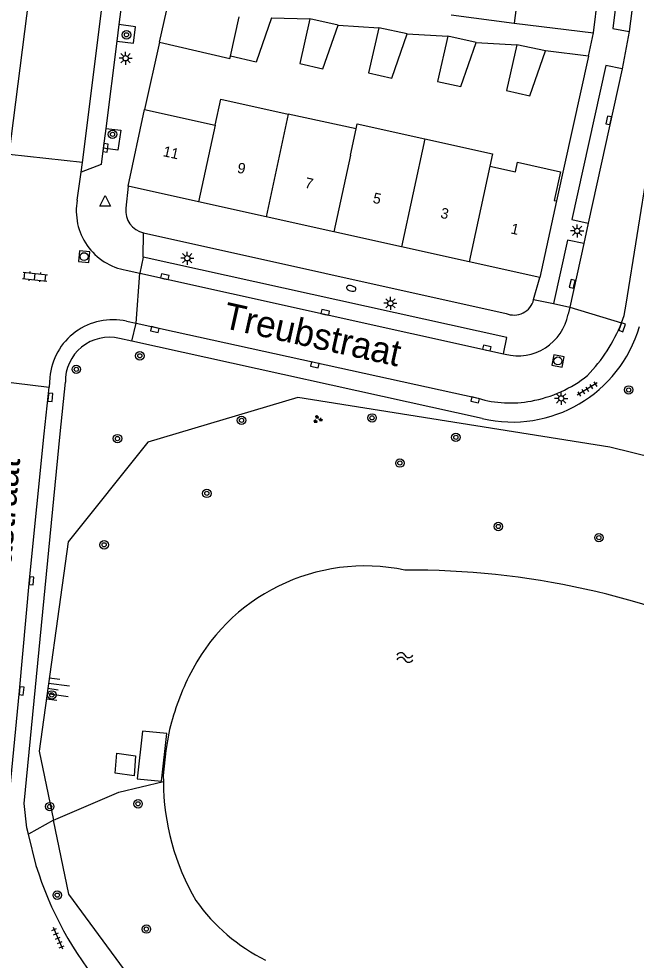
# Model space of a CAD drawing. Extents: x 131000 to 133014, y 396499 to 399001.
# Drawn here: x 131743 to 131801.6, y 397450 to 397539.4 of the extents above; entities that cross this region are included whole.
import ezdxf

# ---------------------------------------------------------------- set-up
doc = ezdxf.new("R2010")
doc.units = 0
for name, color, linetype in [('gg-afsc-erfafscheiding', 7, 'Continuous'), ('gg-afsc-muur', 7, 'Continuous'), ('gg-anno-huisnummerreeks BGT', 7, 'Continuous'), ('gg-anno-openbare ruimte label', 7, 'Continuous'), ('gg-bbg-bijgebouw', 7, 'Continuous'), ('gg-bbg-gedigitaliseerde bebouwing', 7, 'Continuous'), ('gg-bbg-gedigitaliseerde bijgebouw', 7, 'Continuous'), ('gg-bbg-hoofdgebouw', 7, 'Continuous'), ('gg-bbg-tussenscheiding', 7, 'Continuous'), ('gg-knt-BGT kruinlijn', 7, 'Continuous'), ('gg-knt-verharding', 7, 'Continuous'), ('gg-knt-verharding nz', 7, 'Continuous'), ('gg-kntw-beschoeiing', 7, 'Continuous'), ('gg-kwrk-betonelement', 7, 'Continuous'), ('gg-kwrk-uitstroombak niveau min 01', 7, 'Continuous'), ('gt-grn-groengrens', 7, 'Continuous'), ('gt-grn-weggrens', 7, 'Continuous'), ('gt-symb-boom', 7, 'Continuous'), ('gt-symb-brandkraan', 7, 'Continuous'), ('gt-symb-groenvak', 7, 'Continuous'), ('gt-symb-klinker verharding', 7, 'Continuous'), ('gt-symb-kolk', 7, 'Continuous'), ('gt-symb-lichtmast', 7, 'Continuous'), ('gt-symb-rioolschacht', 7, 'Continuous'), ('gt-symb-talud symbool', 7, 'Continuous'), ('gt-symb-tegel verharding', 7, 'Continuous'), ('gt-symb-waterafsluiter', 7, 'Continuous'), ('gt-symb-watersymbool', 7, 'Continuous')]:
    doc.layers.add(name, color=color, linetype=linetype)

# ---------------------------------------------------------------- blocks, each defined once
blk = doc.blocks.new('gt0-KOLK')
at = {"layer": 'gt-symb-kolk'}
blk.add_lwpolyline([(0, 0), (0.375, 0), (0.375, 0.4), (-0.375, 0.4), (-0.375, 0), (0, 0)], dxfattribs=at)
blk = doc.blocks.new('gt0-BOOM')
at = {"layer": 'gt-symb-boom'}
for radius in [0.4, 0.2]:
    blk.add_circle((0, 0), radius, dxfattribs=at)
blk = doc.blocks.new('gt0-LMAST')
at = {"layer": 'gt-symb-lichtmast'}
for p, q in [((-0.182, 0.173), (-0.447, 0.438)), ((-0.005, 0.246), (-0.005, 0.621)), ((0.172, 0.173), (0.437, 0.438)), ((-0.255, -0.004), (-0.63, -0.004)), ((-0.182, -0.181), (-0.447, -0.446)), ((-0.005, -0.254), (-0.005, -0.629)), ((0.437, -0.446), (0.172, -0.181)), ((0.245, -0.004), (0.62, -0.004))]:
    blk.add_line(p, q, dxfattribs=at)
blk.add_circle((-0.005, -0.004), 0.25, dxfattribs=at)
blk = doc.blocks.new('gt0-RS')
at = {"layer": 'gt-symb-rioolschacht'}
blk.add_lwpolyline([(-0.5, -0.5), (0.5, -0.5), (0.5, 0.5), (-0.5, 0.5)], close=True, dxfattribs=at)
blk.add_circle((0, 0), 0.375, dxfattribs=at)
blk = doc.blocks.new('gt0-WAFSL')
at = {"layer": 'gt-symb-waterafsluiter'}
for p, q in [((-0.5, -0.333), (0, 0.667)), ((0, 0.667), (0.5, -0.333)), ((0.5, -0.333), (-0.5, -0.333))]:
    blk.add_line(p, q, dxfattribs=at)
blk = doc.blocks.new('gt0-BR')
at = {"layer": 'gt-symb-brandkraan'}
for centre, radius, start, end in [((-0.244, 0), 0.206, 107.56694, 252.43307), ((0.599, -2.664), 3, 106.89205, 107.56694), ((0, -0.691), 0.938, 73.10799, 106.89205), ((-0.599, -2.664), 3, 72.43309, 73.10799), ((0.244, 0), 0.206, 287.56695, 72.43309), ((0.599, 2.664), 3, 252.43307, 253.10797), ((0, 0.691), 0.938, 253.10797, 286.89206), ((-0.599, 2.664), 3, 286.89206, 287.56695)]:
    blk.add_arc(centre, radius, start, end, dxfattribs=at)
blk = doc.blocks.new('gt0-TEG1')
at = {"layer": 'gt-symb-tegel verharding'}
for p, q in [((-1.125, 0), (1.125, 0)), ((-0.9, -0.25), (-0.9, 0.25)), ((-0.45, -0.25), (-0.45, 0.25)), ((0, -0.25), (0, 0.25)), ((0.45, -0.25), (0.45, 0.25)), ((0.9, -0.25), (0.9, 0.25))]:
    blk.add_line(p, q, dxfattribs=at)
blk = doc.blocks.new('gt0-KL1')
at = {"layer": 'gt-symb-klinker verharding'}
for p, q in [((-1.15, 0.3), (1.15, 0.3)), ((-1, -0.3), (-1, 0.3)), ((-0.5, 0.3), (-0.5, 0.45)), ((0, -0.3), (0, 0.3)), ((0.5, 0.3), (0.5, 0.45)), ((1, -0.3), (1, 0.3)), ((-1.15, -0.3), (1.15, -0.3)), ((-0.5, -0.45), (-0.5, -0.3)), ((0.5, -0.45), (0.5, -0.3))]:
    blk.add_line(p, q, dxfattribs=at)
blk = doc.blocks.new('gt0-TALUD_1')
at = {"layer": 'gt-symb-talud symbool'}
for p, q in [((0, -1), (0, 0)), ((-1, -1), (-1, 0)), ((-0.5, -2), (-0.5, 0)), ((0.5, -2), (0.5, 0)), ((1, -1), (1, 0))]:
    blk.add_line(p, q, dxfattribs=at)
blk = doc.blocks.new('gt0-WA')
at = {"layer": 'gt-symb-watersymbool'}
for centre, start, end in [((-0.323, 0.022), 28.07249, 151.92751), ((0.427, 0.422), 208.07248, 331.92751), ((-0.323, -0.428), 28.07249, 151.92751), ((0.427, -0.028), 208.07248, 331.92751)]:
    blk.add_arc(centre, 0.425, start, end, dxfattribs=at)
blk = doc.blocks.new('gt0-GRVAK')
at = {"layer": 'gt-symb-groenvak'}
for p, q in [((-0.11, 0.189), (-0.228, 0.24)), ((-0.182, 0.153), (0.088, 0.153)), ((-0.091, 0.211), (-0.156, 0.322)), ((-0.047, 0.214), (-0.047, 0.393)), ((-0.004, 0.211), (0.061, 0.322)), ((0.015, 0.189), (0.133, 0.24)), ((0.262, -0.052), (0.197, 0.059)), ((0.305, -0.049), (0.305, 0.13)), ((0.349, -0.052), (0.414, 0.059)), ((-0.245, -0.228), (-0.363, -0.177)), ((-0.318, -0.264), (-0.047, -0.264)), ((-0.226, -0.206), (-0.291, -0.095)), ((-0.183, -0.203), (-0.183, -0.024)), ((-0.139, -0.206), (-0.074, -0.095)), ((-0.12, -0.228), (-0.002, -0.177)), ((0.243, -0.074), (0.125, -0.023)), ((0.17, -0.11), (0.441, -0.11)), ((0.368, -0.074), (0.486, -0.023))]:
    blk.add_line(p, q, dxfattribs=at)

msp = doc.modelspace()

# ---------------------------------------------------------------- linework, layer by layer
at = {"layer": 'gg-afsc-erfafscheiding'}
for p, q in [((131784.068, 397539.788), (131790.053, 397539.004)), ((131767.02, 397539.514), (131770.659, 397539.408)), ((131779.898, 397537.994), (131783.763, 397537.787))]:
    msp.add_line(p, q, dxfattribs=at)
at = {"layer": 'gg-afsc-muur'}
for p, q in [((131773.356, 397538.831), (131777.198, 397538.569)), ((131756.39, 397537.19), (131754.98, 397530.82)), ((131786.453, 397537.184), (131790.295, 397536.958)), ((131797.085, 397535.883), (131793.018, 397536.379)), ((131797.085, 397535.883), (131794.05, 397522.13))]:
    msp.add_line(p, q, dxfattribs=at)
at = {"layer": 'gg-bbg-bijgebouw'}
for p, q in [((131756.39, 397537.19), (131757.29, 397541.13)), ((131773.356, 397538.831), (131770.659, 397539.408)), ((131779.898, 397537.994), (131777.198, 397538.569)), ((131786.453, 397537.184), (131783.763, 397537.787)), ((131793.018, 397536.379), (131790.295, 397536.958))]:
    msp.add_line(p, q, dxfattribs=at)
at = {"layer": 'gg-bbg-gedigitaliseerde bebouwing'}
for p, q in [((131790.814, 397545.191), (131790.053, 397539.004)), ((131790.053, 397539.004), (131797.57, 397538.08)), ((131754.98, 397530.82), (131761.666, 397529.333)), ((131775.043, 397528.969), (131768.613, 397530.364))]:
    msp.add_line(p, q, dxfattribs=at)
for points in [[(131761.666, 397529.333), (131762.212, 397531.788), (131768.613, 397530.364)], [(131775.043, 397528.969), (131775.152, 397529.457), (131781.582, 397528.026)], [(131781.582, 397528.026), (131788.005, 397526.597), (131787.744, 397525.423)], [(131787.744, 397525.423), (131790.163, 397524.885), (131790.369, 397525.811), (131794.453, 397524.902), (131793.847, 397522.175), (131794.05, 397522.13)]]:
    msp.add_lwpolyline(points, dxfattribs=at)
at = {"layer": 'gg-bbg-gedigitaliseerde bijgebouw'}
for points in [[(131767.02, 397539.514), (131765.555, 397535.31), (131763.124, 397535.861)], [(131770.659, 397539.408), (131769.698, 397535.169), (131771.904, 397534.668), (131773.356, 397538.831)], [(131777.198, 397538.569), (131776.228, 397534.289), (131778.432, 397533.789), (131779.898, 397537.994)], [(131756.39, 397537.19), (131763.081, 397535.668), (131763.124, 397535.861)], [(131783.763, 397537.787), (131782.786, 397533.476), (131784.986, 397532.978), (131786.453, 397537.184)], [(131790.295, 397536.958), (131789.306, 397532.599), (131791.524, 397532.096), (131793.018, 397536.379)]]:
    msp.add_lwpolyline(points, dxfattribs=at)
at = {"layer": 'gg-bbg-hoofdgebouw'}
for p, q in [((131797.57, 397538.08), (131798.332, 397544.261)), ((131753.41, 397523.53), (131754.98, 397530.82)), ((131760.096, 397522.043), (131753.41, 397523.53)), ((131766.509, 397520.616), (131760.096, 397522.043)), ((131794.05, 397522.13), (131792.47, 397514.84)), ((131772.932, 397519.187), (131766.509, 397520.616)), ((131779.34, 397517.761), (131772.932, 397519.187)), ((131785.762, 397516.332), (131779.34, 397517.761)), ((131792.47, 397514.84), (131785.762, 397516.332))]:
    msp.add_line(p, q, dxfattribs=at)
at = {"layer": 'gg-bbg-tussenscheiding'}
for p, q in [((131763.124, 397535.861), (131763.961, 397539.612)), ((131768.613, 397530.364), (131766.509, 397520.616)), ((131761.666, 397529.333), (131760.096, 397522.043)), ((131774.503, 397526.478), (131775.043, 397528.969)), ((131781.582, 397528.026), (131779.34, 397517.761)), ((131774.503, 397526.478), (131772.932, 397519.187)), ((131787.744, 397525.423), (131785.762, 397516.332))]:
    msp.add_line(p, q, dxfattribs=at)
at = {"layer": 'gg-knt-BGT kruinlijn'}
for points in [[(131861.13, 397483.46), (131799.11, 397498.73), (131769.52, 397503.47), (131755.28, 397499.23), (131747.72, 397489.76), (131744.99, 397469.87), (131746.339, 397463.325)], [(131762.43, 397442.7), (131753.86, 397448.04), (131747.79, 397456.29), (131746.339, 397463.325)]]:
    msp.add_lwpolyline(points, dxfattribs=at)
at = {"layer": 'gg-knt-verharding'}
for p, q in [((131742.143, 397526.534), (131744.895, 397548.371)), ((131752.549, 397538.875), (131752.35, 397537.307)), ((131800.971, 397538.206), (131800.292, 397534.668)), ((131752.35, 397537.307), (131751.301, 397529.017)), ((131751.301, 397529.017), (131751.062, 397527.129)), ((131749.079, 397525.772), (131742.143, 397526.534)), ((131748.955, 397524.858), (131749.079, 397525.772)), ((131748.595, 397522.212), (131748.955, 397524.858)), ((131753.41, 397523.53), (131753.19, 397521.44)), ((131797.072, 397520.014), (131796.653, 397518.073)), ((131754.879, 397519.1), (131789.28, 397511.44)), ((131754.842, 397516.784), (131754.519, 397515.26)), ((131753.238, 397515.547), (131754.519, 397515.26)), ((131754.175, 397510.508), (131754.519, 397515.26)), ((131791.895, 397512.753), (131792.47, 397514.84)), ((131793.768, 397512.396), (131795.313, 397512.032)), ((131795.313, 397512.032), (131795.165, 397511.366)), ((131753.263, 397510.709), (131754.175, 397510.508)), ((131754.175, 397510.508), (131786.634, 397503.382)), ((131753.772, 397508.797), (131752.584, 397509.059)), ((131787.016, 397501.456), (131753.772, 397508.797)), ((131789.03, 397507.605), (131789.206, 397507.566)), ((131739.953, 397505.185), (131745.915, 397504.45)), ((131745.994, 397505.364), (131745.915, 397504.45)), ((131745.464, 397500), (131745.915, 397504.45)), ((131746.983, 397500), (131747.468, 397504.915)), ((131744.675, 397459.029), (131743.963, 397461.997))]:
    msp.add_line(p, q, dxfattribs=at)
for points in [[(131803.137, 397555.819), (131801.569, 397556.036), (131799.411, 397538.498), (131800.971, 397538.206)], [(131753.781, 397548.468), (131753.32, 397544.967), (131752.549, 397538.875)], [(131752.35, 397537.307), (131753.935, 397537.106), (131754.131, 397538.675), (131752.549, 397538.875)], [(131800.292, 397534.668), (131798.737, 397534.977), (131795.513, 397520.351), (131797.072, 397520.014)], [(131751.301, 397529.017), (131752.717, 397528.838), (131752.455, 397526.953), (131751.062, 397527.129)], [(131751.062, 397527.129), (131750.867, 397525.586), (131748.955, 397524.858)], [(131800.232, 397510.549), (131800.478, 397511.242), (131800.672, 397512.334), (131802.768, 397525.352)], [(131796.653, 397518.073), (131795.103, 397518.403), (131793.768, 397512.396)], [(131789.03, 397507.605), (131789.345, 397509.155), (131754.842, 397516.784)], [(131740.962, 397452.964), (131741.081, 397454.971), (131743.11, 397475.613), (131744.057, 397486.134), (131745.464, 397500)], [(131743.963, 397461.997), (131743.817, 397462.604), (131743.566, 397464.92), (131746.983, 397500)]]:
    msp.add_lwpolyline(points, dxfattribs=at)
for centre, radius, start, end in [((131754.195, 397521.163), 5.697, 169.3939, 260.3301), ((131755.352, 397521.221), 2.173, 174.20995, 257.43317), ((131790.026, 397513.214), 1.925, 247.18109, 346.14167), ((131790.4, 397512.266), 4.849, 255.74356, 349.30702), ((131751.971, 397504.851), 5.999, 77.55763, 175.09753), ((131785.639, 397516.409), 15.726, 316.3461, 338.1197), ((131789.859, 397513.694), 12.564, 256.92315, 343.89976), ((131751.611, 397505.031), 4.144, 76.41382, 181.60166), ((131789.478, 397515.054), 12.128, 280.31171, 308.43459), ((131789.675, 397513.546), 10.609, 253.34238, 280.72199), ((131776.2, 397468.638), 32.957, 196.95067, 220.41016)]:
    msp.add_arc(centre, radius, start, end, dxfattribs=at)
at = {"layer": 'gg-knt-verharding nz'}
for p, q in [((131749.079, 397525.772), (131751.931, 397548.391)), ((131800.292, 397534.668), (131797.072, 397520.014)), ((131796.653, 397518.073), (131795.313, 397512.032)), ((131754.519, 397515.26), (131789.03, 397507.605))]:
    msp.add_line(p, q, dxfattribs=at)
msp.add_lwpolyline([(131803.137, 397555.819), (131801.883, 397545.378), (131800.971, 397538.206)], dxfattribs=at)
at = {"layer": 'gg-kntw-beschoeiing'}
msp.add_lwpolyline([(131757.276, 397471.572), (131756.983, 397469.934), (131756.736, 397467.568), (131756.764, 397467.003)], dxfattribs=at)
msp.add_lwpolyline([(131757.276, 397471.572), (131756.983, 397469.934), (131756.736, 397467.568), (131756.764, 397467.003)], dxfattribs=at)
for centre, radius, start, end in [((131775.864, 397468.96), 18.499, 78.07741, 154.39807), ((131775.864, 397468.96), 18.499, 78.07741, 154.39807), ((131780.412, 397411.771), 75.292, 64.37841, 90.55231), ((131780.412, 397411.771), 75.292, 64.37841, 90.55231), ((131779.717, 397466.653), 22.974, 153.36064, 167.63683), ((131779.717, 397466.653), 22.974, 153.36064, 167.63683), ((131779.372, 397467.082), 22.608, 180.20048, 210.27892), ((131779.372, 397467.082), 22.608, 180.20048, 210.27892), ((131774.323, 397465.916), 17.727, 215.25817, 243.68629), ((131774.323, 397465.916), 17.727, 215.25817, 243.68629)]:
    msp.add_arc(centre, radius, start, end, dxfattribs=at)
at = {"layer": 'gg-kwrk-betonelement'}
msp.add_lwpolyline([(131754.12, 397469.422), (131753.984, 397467.524), (131752.198, 397467.792), (131752.333, 397469.689), (131754.12, 397469.422)], dxfattribs=at)
at = {"layer": 'gg-kwrk-uitstroombak niveau min 01'}
msp.add_lwpolyline([(131754.262, 397467.257), (131756.568, 397467.014), (131757.088, 397471.542), (131754.782, 397471.784), (131754.262, 397467.257)], dxfattribs=at)
at = {"layer": 'gt-grn-groengrens'}
msp.add_line((131746.339, 397463.325), (131743.963, 397461.997), dxfattribs=at)
msp.add_lwpolyline([(131746.339, 397463.325), (131752.539, 397465.97), (131756.764, 397467.003)], dxfattribs=at)
at = {"layer": 'gt-grn-weggrens'}
for p, q in [((131797.085, 397535.883), (131797.57, 397538.08)), ((131754.842, 397516.784), (131754.879, 397519.1)), ((131791.895, 397512.753), (131793.768, 397512.396)), ((131795.313, 397512.032), (131800.232, 397510.549)), ((131753.772, 397508.797), (131754.175, 397510.508))]:
    msp.add_line(p, q, dxfattribs=at)

# ---------------------------------------------------------------- block references
at = {"layer": 'gt-symb-boom', "rotation": 90}
for p in [(131753.258, 397537.902), (131751.935, 397528.451), (131754.527, 397507.42), (131748.497, 397506.135)]:
    msp.add_blockref('gt0-BOOM', p, dxfattribs=at)
at = {"layer": 'gt-symb-boom'}
for p in [(131800.911, 397504.175), (131764.178, 397501.293), (131776.56, 397501.524), (131752.405, 397499.556), (131784.515, 397499.676), (131779.202, 397497.234), (131760.885, 397494.356), (131788.543, 397491.211), (131751.14, 397489.47), (131798.084, 397490.149), (131746.173, 397475.215), (131745.976, 397464.611), (131754.357, 397464.876), (131746.69, 397456.203), (131755.148, 397452.978)]:
    msp.add_blockref('gt0-BOOM', p, dxfattribs=at)
at = {"layer": 'gt-symb-brandkraan', "rotation": 165.17189147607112}
msp.add_blockref('gt0-BR', (131774.586, 397513.822), dxfattribs=at)
at = {"layer": 'gt-symb-groenvak'}
msp.add_blockref('gt0-GRVAK', (131771.393, 397501.389), dxfattribs=at)
at = {"layer": 'gt-symb-klinker verharding', "rotation": -6.030008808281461}
msp.add_blockref('gt0-KL1', (131744.576, 397514.931), dxfattribs=at)
at = {"layer": 'gt-symb-kolk'}
for p, rotation in [((131799.209, 397529.738), 77.58922528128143), ((131751.065, 397527.193), -96.89054832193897), ((131756.848, 397514.744), -12.410774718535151), ((131795.751, 397514.202), 76.88085536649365), ((131772.083, 397511.356), -12.535023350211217), ((131800.107, 397510.197), -110.1201657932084), ((131755.995, 397510.107), 167.40904938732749), ((131787.418, 397507.961), -12.535023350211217), ((131771.18, 397506.76), 167.52092819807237), ((131745.84, 397503.496), -95.68208493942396), ((131786.383, 397503.427), 167.589225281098), ((131744.051, 397486.07), -95.14766758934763), ((131743.11, 397475.613), -95.68208494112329)]:
    msp.add_blockref('gt0-KOLK', p, dxfattribs=dict(at, rotation=rotation))
at = {"layer": 'gt-symb-lichtmast'}
for p in [(131753.185, 397535.679), (131796.024, 397519.283), (131759.032, 397516.687), (131778.307, 397512.407), (131794.507, 397503.377)]:
    msp.add_blockref('gt0-LMAST', p, dxfattribs=at)
at = {"layer": 'gt-symb-rioolschacht'}
for p, rotation in [((131749.24, 397516.837), -5.2774060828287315), ((131794.2, 397506.933), -101.07387115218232)]:
    msp.add_blockref('gt0-RS', p, dxfattribs=dict(at, rotation=rotation))
at = {"layer": 'gt-symb-talud symbool', "xscale": 1.00028845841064, "yscale": 1.0002884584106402, "rotation": 82.18581914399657}
msp.add_blockref('gt0-TALUD_1', (131745.799, 397475.81), dxfattribs=at)
at = {"layer": 'gt-symb-tegel verharding'}
for p, rotation in [((131796.977, 397504.258), -148.53512697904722), ((131746.753, 397452.12), -66.30502896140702)]:
    msp.add_blockref('gt0-TEG1', p, dxfattribs=dict(at, rotation=rotation))
at = {"layer": 'gt-symb-waterafsluiter'}
msp.add_blockref('gt0-WAFSL', (131751.238, 397521.962), dxfattribs=at)
at = {"layer": 'gt-symb-watersymbool'}
msp.add_blockref('gt0-WA', (131779.62, 397478.772), dxfattribs=at)

# ---------------------------------------------------------------- texts
at = {"layer": 'gg-anno-huisnummerreeks BGT'}
for s, p in [('11', (131756.662, 397526.391)), ('9', (131763.705, 397524.825)), ('7', (131770.12, 397523.398)), ('5', (131776.574, 397521.962)), ('3', (131782.989, 397520.534)), ('1', (131789.659, 397519.05))]:
    msp.add_text(s, height=1, rotation=347.5, dxfattribs=at).set_placement(p)
at = {"layer": 'gg-anno-openbare ruimte label'}
for s, rotation, p in [('Treubstraat', 347.5, (131762.287, 397510.092)), ('Troelstrastraat', 85.1, (131741.332, 397476.169))]:
    msp.add_text(s, height=2.5, rotation=rotation, dxfattribs=at).set_placement(p)

doc.saveas('drawing.dxf')
